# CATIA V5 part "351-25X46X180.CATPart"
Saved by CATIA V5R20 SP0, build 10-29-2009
Part number: 351-25X46X180
Definition: NONE
Nomenclature: 351-25X46X180
Source: Unknown
Description: 351-25X46X180
Bounding box of the stored display mesh (mm): x -7 to 173, y -19 to 19, z -19 to 19
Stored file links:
  C:\Users\Utente\Desktop\IO LAVORO\3D X SITO CF\X SITO\PLASTICA\351\351-25X46X180.CATPart
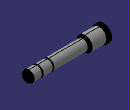
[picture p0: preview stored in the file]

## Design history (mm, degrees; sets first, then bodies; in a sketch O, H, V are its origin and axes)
Body1 "351-25X46X180" (main body)
  Solid1: solid without history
